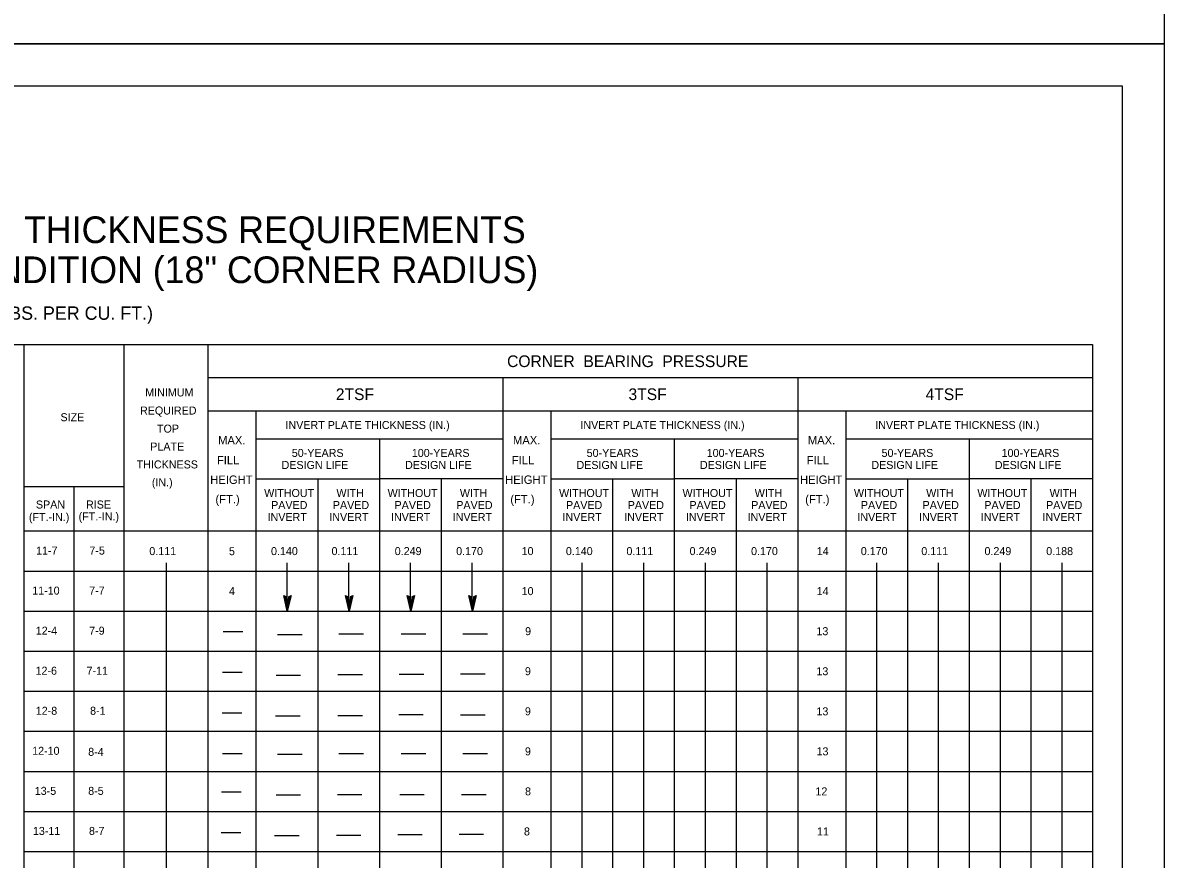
# Model space of a CAD drawing. Extents: x 591 to 2288, y -189 to 2187.
# Drawn here: x 1864.7 to 2273.3, y 1301.4 to 1600.7 of the extents above; entities that cross this region are included whole.
import ezdxf

# ---------------------------------------------------------------- set-up
doc = ezdxf.new("R2010")
doc.units = 0
for name, color, linetype in [('1', 7, 'Continuous'), ('2', 7, 'Continuous'), ('PLT-BNDY', 7, 'Continuous')]:
    doc.layers.add(name, color=color, linetype=linetype)

msp = doc.modelspace()

# ---------------------------------------------------------------- linework, layer by layer
at = {"layer": '1'}
for p, q in [((1481.73, 1485.59), (2247.72, 1485.59)), ((1865.08, 1485.59), (1865.08, 1176.64)), ((1900.91, 1485.59), (1900.91, 1176.64)), ((1931.01, 1485.59), (1931.01, 1176.64)), ((2247.72, 1485.59), (2247.72, 1176.64)), ((2247.72, 1473.72), (1931.01, 1473.72)), ((2036.58, 1473.72), (2036.58, 1176.64)), ((2142.15, 1473.72), (2142.15, 1176.64)), ((1931.01, 1461.85), (2036.58, 1461.85)), ((1948.19, 1461.85), (1948.19, 1176.64)), ((2036.58, 1461.85), (2142.15, 1461.85)), ((2053.76, 1461.85), (2053.76, 1176.64)), ((2142.15, 1461.85), (2247.72, 1461.85)), ((2159.33, 1461.85), (2159.33, 1176.64)), ((1948.19, 1451.82), (2036.58, 1451.82)), ((1992.38, 1451.82), (1992.38, 1176.64)), ((2053.76, 1451.82), (2142.15, 1451.82)), ((2097.95, 1451.82), (2097.95, 1176.64)), ((2159.33, 1451.82), (2247.72, 1451.82)), ((2203.52, 1451.82), (2203.52, 1176.64)), ((1900.91, 1434.62), (1865.08, 1434.62)), ((1883, 1434.62), (1883, 1176.64)), ((1948.19, 1437.48), (1992.38, 1437.48)), ((1970.29, 1437.48), (1970.29, 1176.64)), ((2036.58, 1437.48), (1992.38, 1437.48)), ((2014.48, 1437.48), (2014.48, 1176.64)), ((2053.76, 1437.48), (2097.95, 1437.48)), ((2075.86, 1437.48), (2075.86, 1176.64)), ((2142.15, 1437.48), (2097.95, 1437.48)), ((2120.05, 1437.48), (2120.05, 1176.64)), ((2159.33, 1437.48), (2203.52, 1437.48)), ((2181.43, 1437.48), (2181.43, 1176.64)), ((2247.72, 1437.48), (2203.52, 1437.48)), ((2225.62, 1437.48), (2225.62, 1176.64)), ((2247.72, 1418.85), (1865.08, 1418.85)), ((1916.1, 1407.43), (1916.1, 1176.64)), ((1959.24, 1407.43), (1959.24, 1390.19)), ((1981.34, 1407.43), (1981.34, 1390.19)), ((2003.43, 1407.43), (2003.43, 1390.19)), ((2025.53, 1407.43), (2025.53, 1390.19)), ((2064.81, 1407.43), (2064.81, 1176.64)), ((2086.91, 1407.43), (2086.91, 1176.64)), ((2109, 1407.43), (2109, 1176.64)), ((2131.1, 1407.43), (2131.1, 1176.64)), ((2170.38, 1407.43), (2170.38, 1176.64)), ((2192.48, 1407.43), (2192.48, 1176.64)), ((2214.57, 1407.43), (2214.57, 1176.64)), ((2236.67, 1407.43), (2236.67, 1176.64)), ((1865.08, 1404.52), (2247.72, 1404.52)), ((1865.08, 1390.19), (2247.72, 1390.19)), ((1936.43, 1382.93), (1943.45, 1382.93)), ((1955.92, 1381.87), (1964.7, 1381.87)), ((1977.87, 1382.05), (1986.65, 1382.05)), ((2000.17, 1382.05), (2008.96, 1382.05)), ((2022.3, 1382.05), (2031.08, 1382.05)), ((1865.08, 1375.86), (2247.72, 1375.86)), ((1936.26, 1368.35), (1943.28, 1368.35)), ((1955.4, 1367.3), (1964.17, 1367.3)), ((1977.52, 1367.47), (1986.3, 1367.47)), ((1999.47, 1367.65), (2008.25, 1367.65)), ((2021.42, 1367.82), (2030.2, 1367.82)), ((1865.08, 1361.52), (2247.72, 1361.52)), ((1936.08, 1353.78), (1943.1, 1353.78)), ((1955.22, 1352.72), (1964, 1352.72)), ((1977.52, 1352.9), (1986.3, 1352.9)), ((1999.3, 1353.25), (2008.08, 1353.25)), ((2021.42, 1353.07), (2030.2, 1353.07)), ((1865.08, 1347.19), (2247.72, 1347.19)), ((1936.26, 1339.2), (1943.28, 1339.2)), ((1955.92, 1339.03), (1964.7, 1339.03)), ((1977.87, 1339.2), (1986.65, 1339.2)), ((2000.17, 1339.2), (2008.96, 1339.2)), ((2022.3, 1339.2), (2031.08, 1339.2)), ((1865.08, 1332.86), (2247.72, 1332.86)), ((1935.9, 1325.5), (1942.93, 1325.5)), ((1955.4, 1324.45), (1964.18, 1324.45)), ((1977.35, 1324.63), (1986.13, 1324.63)), ((1999.65, 1324.63), (2008.43, 1324.63)), ((2021.78, 1324.63), (2030.55, 1324.63)), ((1865.08, 1318.53), (2247.72, 1318.53)), ((1935.73, 1310.93), (1942.75, 1310.93)), ((1954.87, 1309.88), (1963.65, 1309.88)), ((1977, 1310.05), (1985.78, 1310.05)), ((1998.95, 1310.23), (2007.73, 1310.23)), ((2020.9, 1310.4), (2029.68, 1310.4)), ((1865.08, 1304.2), (2247.72, 1304.2))]:
    msp.add_line(p, q, dxfattribs=at)
for points in [[(1960.39, 1395.55), (1959.83, 1395.35), (1959.41, 1390.13), (1960.39, 1395.55), (1960.74, 1395.83), (1959.41, 1390.13), (1959.04, 1395.35), (1958.48, 1395.54), (1959.41, 1390.13), (1958.11, 1395.83), (1958.48, 1395.54)], [(1982.49, 1395.55), (1981.93, 1395.35), (1981.51, 1390.13), (1982.49, 1395.55), (1982.84, 1395.83), (1981.51, 1390.13), (1981.14, 1395.35), (1980.58, 1395.54), (1981.51, 1390.13), (1980.21, 1395.83), (1980.58, 1395.54)], [(2004.59, 1395.55), (2004.02, 1395.35), (2003.61, 1390.13), (2004.59, 1395.55), (2004.93, 1395.83), (2003.61, 1390.13), (2003.23, 1395.35), (2002.68, 1395.54), (2003.61, 1390.13), (2002.3, 1395.83), (2002.68, 1395.54)], [(2026.69, 1395.55), (2026.12, 1395.35), (2025.71, 1390.13), (2026.69, 1395.55), (2027.03, 1395.83), (2025.71, 1390.13), (2025.34, 1395.35), (2024.77, 1395.54), (2025.71, 1390.13), (2024.4, 1395.83), (2024.77, 1395.54)]]:
    msp.add_lwpolyline(points, dxfattribs=at)
at = {"layer": '2'}
for p, q in [((1472.34, 1578.21), (2258.34, 1578.21)), ((2258.34, 1578.21), (2258.34, 1014.21))]:
    msp.add_line(p, q, dxfattribs=at)
at = {"layer": 'PLT-BNDY'}
for points in [[(1432.34, 2187.21), (2273.34, 2187.21), (2273.34, 1593.21), (1432.34, 1593.21)], [(1432.34, 1593.21), (2273.34, 1593.21), (2273.34, 999.21), (1432.34, 999.21)]]:
    msp.add_lwpolyline(points, close=True, dxfattribs=at)

# ---------------------------------------------------------------- texts
at = {"layer": '1'}
for s, height, p in [('STEEL STRUCTURAL PLATE PIPE-ARCH THICKNESS REQUIREMENTS', 9.5546, (1614.55, 1521.89)), ('WITH MINIMUM  PREDICTED METAL LOSS CONDITION (18" CORNER RADIUS)', 9.5546, (1574.08, 1507.57)), ('(BACKFILL UNIT WEIGHT = 140 LBS. PER CU. FT.)', 4.7773, (1760.29, 1494.45)), ('CORNER  BEARING  PRESSURE', 4.1801, (2038.09, 1477.53)), ('MINIMUM', 2.866, (1908.55, 1467.03)), ('2TSF', 4.18, (1976.78, 1465.72)), ('3TSF', 4.18, (2081.56, 1465.72)), ('4TSF', 4.18, (2187.92, 1465.72)), ('REQUIRED', 2.866, (1906.68, 1460.55)), ('SIZE', 2.866, (1878.21, 1458.15)), ('TOP', 2.866, (1912.77, 1454.07)), ('INVERT PLATE THICKNESS (IN.)', 2.8664, (1958.76, 1455.37)), ('INVERT PLATE THICKNESS (IN.)', 2.8664, (2064.34, 1455.37)), ('INVERT PLATE THICKNESS (IN.)', 2.8664, (2169.9, 1455.37)), ('PLATE', 2.866, (1910.35, 1447.67)), ('50-YEARS', 2.866, (1961.02, 1445.37)), ('100-YEARS', 2.866, (2003.99, 1445.37)), ('50-YEARS', 2.866, (2066.59, 1445.37)), ('100-YEARS', 2.866, (2109.56, 1445.37)), ('50-YEARS', 2.866, (2172.16, 1445.37)), ('100-YEARS', 2.866, (2215.13, 1445.37)), ('THICKNESS', 2.866, (1905.48, 1441.26)), ('DESIGN LIFE', 2.8664, (1957.37, 1441.07)), ('DESIGN LIFE', 2.8664, (2001.56, 1441.07)), ('DESIGN LIFE', 2.8664, (2062.94, 1441.07)), ('DESIGN LIFE', 2.8664, (2107.13, 1441.07)), ('DESIGN LIFE', 2.8664, (2168.51, 1441.07)), ('DESIGN LIFE', 2.8664, (2212.7, 1441.07)), ('(IN.)', 2.866, (1910.91, 1434.86)), ('WITHOUT', 2.866, (1951.13, 1431.03)), ('WITH', 2.866, (1977, 1431.03)), ('WITHOUT', 2.866, (1995.33, 1431.03)), ('WITH', 2.866, (2021.19, 1431.03)), ('WITHOUT', 2.866, (2056.7, 1431.03)), ('WITH', 2.866, (2082.57, 1431.03)), ('WITHOUT', 2.866, (2100.89, 1431.03)), ('WITH', 2.866, (2126.76, 1431.03)), ('WITHOUT', 2.866, (2162.27, 1431.03)), ('WITH', 2.866, (2188.14, 1431.03)), ('WITHOUT', 2.866, (2206.46, 1431.03)), ('WITH', 2.866, (2232.33, 1431.03)), ('SPAN', 2.866, (1869.41, 1426.92)), ('RISE', 2.866, (1887.34, 1426.92)), ('PAVED', 2.866, (1953.62, 1426.73)), ('PAVED', 2.866, (1975.71, 1426.73)), ('PAVED', 2.866, (1997.81, 1426.73)), ('PAVED', 2.866, (2019.91, 1426.73)), ('PAVED', 2.866, (2059.19, 1426.73)), ('PAVED', 2.866, (2081.28, 1426.73)), ('PAVED', 2.866, (2103.38, 1426.73)), ('PAVED', 2.866, (2125.48, 1426.73)), ('PAVED', 2.866, (2164.76, 1426.73)), ('PAVED', 2.866, (2186.85, 1426.73)), ('PAVED', 2.866, (2208.95, 1426.73)), ('PAVED', 2.866, (2231.05, 1426.73)), ('(FT.-IN.)', 2.866, (1866.9, 1422.45)), ('(FT.-IN.)', 2.866, (1884.7, 1422.65)), ('INVERT', 2.866, (1952.35, 1422.44)), ('INVERT', 2.866, (1974.45, 1422.44)), ('INVERT', 2.866, (1996.54, 1422.44)), ('INVERT', 2.866, (2018.64, 1422.44)), ('INVERT', 2.866, (2057.92, 1422.44)), ('INVERT', 2.866, (2080.02, 1422.44)), ('INVERT', 2.866, (2102.11, 1422.44)), ('INVERT', 2.866, (2124.21, 1422.44)), ('INVERT', 2.866, (2163.49, 1422.44)), ('INVERT', 2.866, (2185.59, 1422.44)), ('INVERT', 2.866, (2207.68, 1422.44)), ('INVERT', 2.866, (2229.78, 1422.44)), ('11-7', 2.866, (1869.48, 1410.44)), ('7-5', 2.866, (1888.55, 1410.44)), ('0.111', 2.866, (1910.01, 1410.25)), ('5', 2.87, (1938.53, 1410.21)), ('0.140', 2.866, (1953.58, 1410.25)), ('0.111', 2.866, (1975.25, 1410.25)), ('0.249', 2.866, (1997.87, 1410.25)), ('0.170', 2.866, (2019.87, 1410.25)), ('10', 2.866, (2043.3, 1410.25)), ('0.140', 2.866, (2059.15, 1410.25)), ('0.111', 2.866, (2080.82, 1410.25)), ('0.249', 2.866, (2103.44, 1410.25)), ('0.170', 2.866, (2125.44, 1410.25)), ('14', 2.866, (2148.97, 1410.25)), ('0.170', 2.866, (2164.72, 1410.25)), ('0.111', 2.866, (2186.39, 1410.25)), ('0.249', 2.866, (2209.01, 1410.25)), ('0.188', 2.866, (2231.12, 1410.25)), ('11-10', 2.866, (1868.09, 1396.11)), ('7-7', 2.866, (1888.48, 1396.11)), ('4', 2.87, (1938.53, 1395.96)), ('10', 2.866, (2043.3, 1395.92)), ('14', 2.866, (2148.91, 1395.92)), ('12-4', 2.866, (1869.35, 1381.77)), ('7-9', 2.866, (1888.47, 1381.77)), ('9', 2.87, (2044.55, 1381.59)), ('13', 2.866, (2148.84, 1381.59)), ('12-6', 2.866, (1869.28, 1367.44)), ('7-11', 2.866, (1887.55, 1367.44)), ('9', 2.87, (2044.48, 1367.26)), ('13', 2.866, (2148.84, 1367.26)), ('12-8', 2.866, (1869.36, 1353.11)), ('8-1', 2.866, (1888.8, 1353.11)), ('9', 2.87, (2044.48, 1352.92)), ('13', 2.866, (2148.85, 1352.92)), ('12-10', 2.866, (1868.06, 1338.78)), ('8-4', 2.866, (1888.13, 1338.41)), ('9', 2.87, (2044.49, 1338.59)), ('13', 2.866, (2148.88, 1338.59)), ('13-5', 2.866, (1869, 1324.45)), ('8-5', 2.866, (1888.13, 1324.45)), ('8', 2.87, (2044.52, 1324.26)), ('12', 2.866, (2148.49, 1324.26)), ('13-11', 2.866, (1868.34, 1310.11)), ('8-7', 2.866, (1888.41, 1310.11)), ('8', 2.87, (2044.14, 1309.93)), ('11', 2.866, (2149.05, 1309.93))]:
    msp.add_text(s, height=height, dxfattribs=at).set_placement(p)
at = {"layer": '2'}
for s, p in [('MAX.', (1934.63, 1449.86)), ('MAX.', (2040.2, 1449.86)), ('MAX.', (2145.77, 1449.86)), ('FILL', (1934.22, 1442.73)), ('FILL', (2039.79, 1442.73)), ('FILL', (2145.35, 1442.73)), ('HEIGHT', (1931.82, 1435.73)), ('HEIGHT', (2037.39, 1435.73)), ('HEIGHT', (2142.96, 1435.73)), ('(FT.)', (1933.68, 1428.73)), ('(FT.)', (2039.25, 1428.73)), ('(FT.)', (2144.82, 1428.73))]:
    msp.add_text(s, height=3, dxfattribs=at).set_placement(p)

doc.saveas('drawing.dxf')
